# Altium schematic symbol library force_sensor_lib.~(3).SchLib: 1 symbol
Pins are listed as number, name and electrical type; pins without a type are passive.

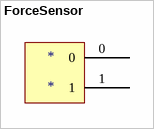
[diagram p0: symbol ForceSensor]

## ForceSensor
designator *
footprint sensor_connector
pins: 0, 1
